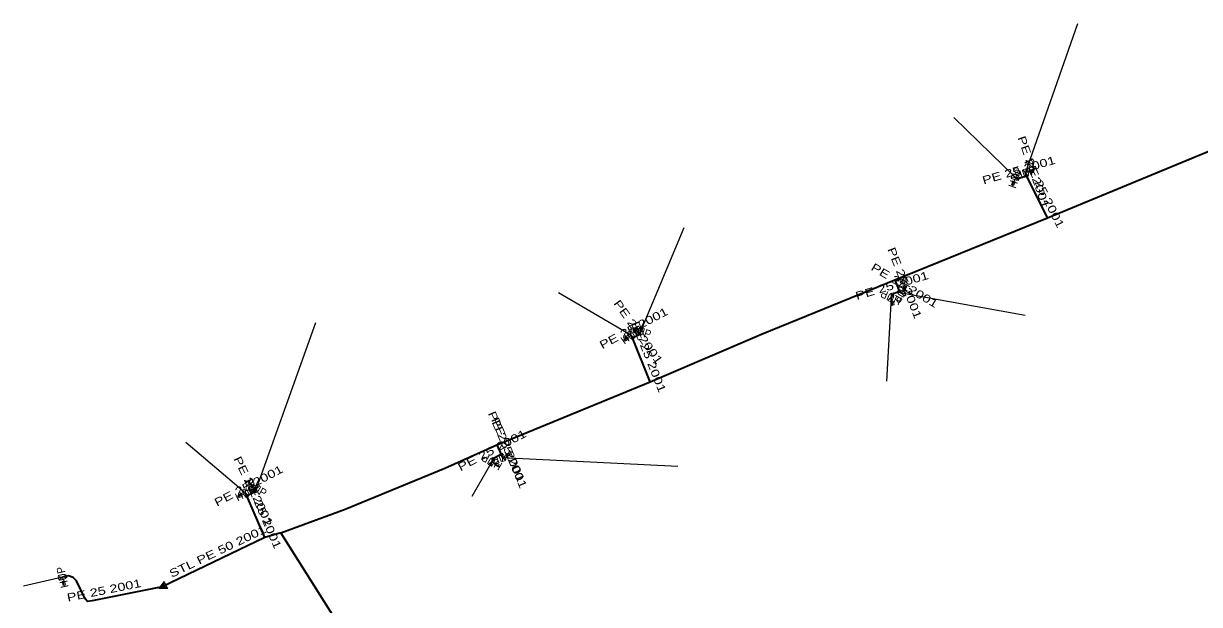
# Model space of a CAD drawing. Extents: x -737484 to -734496, y -1033882 to -1030666.
# Drawn here: x -735181.8 to -735034.9, y -1033442.1 to -1033369.5 of the extents above; entities that cross this region are included whole.
import ezdxf
from ezdxf.enums import TextEntityAlignment as Align

# ---------------------------------------------------------------- set-up
doc = ezdxf.new("R2010")
doc.units = 0
doc.header["$LTSCALE"] = 0.4
for name, color, linetype, lineweight in [('1', 7, 'Continuous', 13), ('22', 7, 'Continuous', 25), ('5', 7, 'Continuous', 35), ('7', 7, 'Continuous', 35)]:
    doc.layers.add(name, color=color, linetype=linetype, lineweight=lineweight)
doc.layers.add('2', color=7, linetype='Continuous')

msp = doc.modelspace()

# ---------------------------------------------------------------- linework, layer by layer
at = {"layer": '1'}
for p, q in [((-735056.61, -1033388.21), (-735056.137, -1033388.047)), ((-735056.041, -1033388.093), (-735055.71, -1033387.979)), ((-735058.148, -1033389.299), (-735058.262, -1033389.63)), ((-735057.89, -1033388.78), (-735058.052, -1033389.252)), ((-735072.11, -1033403.18), (-735071.852, -1033402.751)), ((-735071.749, -1033402.725), (-735071.569, -1033402.425)), ((-735073.41, -1033403.743), (-735073.297, -1033404.23)), ((-735073.353, -1033404.32), (-735073.274, -1033404.661)), ((-735105.93, -1033408.48), (-735106.329, -1033408.78)), ((-735105.221, -1033407.721), (-735105.554, -1033407.613)), ((-735104.698, -1033407.971), (-735105.173, -1033407.816)), ((-735106.434, -1033408.766), (-735106.713, -1033408.976)), ((-735123.31, -1033424.28), (-735122.872, -1033424.522)), ((-735122.843, -1033424.624), (-735122.537, -1033424.794)), ((-735121.97, -1033423.72), (-735121.509, -1033423.524)), ((-735121.411, -1033423.564), (-735121.089, -1033423.427)), ((-735153.16, -1033427.277), (-735153.463, -1033427.102)), ((-735152.7, -1033427.63), (-735153.133, -1033427.38)), ((-735154.609, -1033428.384), (-735154.924, -1033428.538)), ((-735154.06, -1033428.2), (-735154.509, -1033428.419)), ((-735176.93, -1033438.7), (-735176.817, -1033439.187)), ((-735176.873, -1033439.277), (-735176.794, -1033439.618))]:
    msp.add_line(p, q, dxfattribs=at)
for points in [[(-735056.961, -1033387.801), (-735056.583, -1033387.671), (-735056.636, -1033388.746), (-735056.258, -1033388.616)], [(-735055.664, -1033387.884), (-735055.713, -1033387.742), (-735056.186, -1033387.905), (-735056.137, -1033388.047)], [(-735055.664, -1033387.884), (-735055.615, -1033388.026), (-735056.088, -1033388.189), (-735056.137, -1033388.047)], [(-735055.688, -1033387.931), (-735055.663, -1033388.002), (-735056.065, -1033388.141), (-735056.09, -1033388.07)], [(-735058.427, -1033388.806), (-735058.297, -1033388.428), (-735057.482, -1033389.131), (-735057.352, -1033388.753)], [(-735058.215, -1033389.725), (-735058.357, -1033389.676), (-735058.194, -1033389.203), (-735058.052, -1033389.252)], [(-735058.238, -1033389.677), (-735058.309, -1033389.653), (-735058.17, -1033389.251), (-735058.099, -1033389.275)], [(-735058.215, -1033389.725), (-735058.073, -1033389.774), (-735057.91, -1033389.301), (-735058.052, -1033389.252)], [(-735071.578, -1033403.265), (-735071.784, -1033403.607), (-735072.435, -1033402.75), (-735072.641, -1033403.092)], [(-735071.594, -1033402.322), (-735071.723, -1033402.245), (-735071.981, -1033402.674), (-735071.852, -1033402.751)], [(-735071.594, -1033402.322), (-735071.466, -1033402.4), (-735071.723, -1033402.828), (-735071.852, -1033402.751)], [(-735071.582, -1033402.374), (-735071.518, -1033402.413), (-735071.737, -1033402.777), (-735071.801, -1033402.738)], [(-735073.439, -1033404.278), (-735073.805, -1033404.115), (-735073.032, -1033403.364), (-735073.398, -1033403.201)], [(-735073.185, -1033404.717), (-735073.331, -1033404.751), (-735073.443, -1033404.263), (-735073.297, -1033404.23)], [(-735073.229, -1033404.688), (-735073.302, -1033404.705), (-735073.398, -1033404.291), (-735073.325, -1033404.274)], [(-735073.185, -1033404.717), (-735073.038, -1033404.683), (-735073.151, -1033404.196), (-735073.297, -1033404.23)], [(-735106.728, -1033409.081), (-735106.818, -1033408.962), (-735106.419, -1033408.661), (-735106.329, -1033408.78)], [(-735106.38, -1033408.185), (-735106.052, -1033407.955), (-735105.807, -1033409.004), (-735105.479, -1033408.774)], [(-735105.649, -1033407.661), (-735105.695, -1033407.804), (-735105.219, -1033407.959), (-735105.173, -1033407.816)], [(-735105.649, -1033407.661), (-735105.602, -1033407.519), (-735105.127, -1033407.673), (-735105.173, -1033407.816)], [(-735105.601, -1033407.638), (-735105.578, -1033407.567), (-735105.174, -1033407.698), (-735105.197, -1033407.769)], [(-735104.726, -1033407.442), (-735104.348, -1033407.572), (-735105.051, -1033408.387), (-735104.673, -1033408.517)], [(-735106.72, -1033409.029), (-735106.765, -1033408.969), (-735106.426, -1033408.713), (-735106.381, -1033408.773)], [(-735106.728, -1033409.081), (-735106.638, -1033409.201), (-735106.239, -1033408.9), (-735106.329, -1033408.78)], [(-735121.59, -1033424.102), (-735121.958, -1033424.258), (-735121.981, -1033423.181), (-735122.349, -1033423.337)], [(-735121.049, -1033423.329), (-735121.108, -1033423.191), (-735121.568, -1033423.386), (-735121.509, -1033423.524)], [(-735121.049, -1033423.329), (-735120.99, -1033423.467), (-735121.451, -1033423.662), (-735121.509, -1033423.524)], [(-735121.07, -1033423.378), (-735121.04, -1033423.447), (-735121.431, -1033423.613), (-735121.461, -1033423.544)], [(-735123.386, -1033424.812), (-735123.733, -1033424.612), (-735122.886, -1033423.945), (-735123.233, -1033423.745)], [(-735122.435, -1033424.764), (-735122.508, -1033424.896), (-735122.945, -1033424.653), (-735122.872, -1033424.522)], [(-735122.486, -1033424.778), (-735122.522, -1033424.844), (-735122.894, -1033424.638), (-735122.858, -1033424.572)], [(-735122.435, -1033424.764), (-735122.362, -1033424.633), (-735122.799, -1033424.391), (-735122.872, -1033424.522)], [(-735154.458, -1033427.837), (-735154.099, -1033427.661), (-735154.02, -1033428.736), (-735153.661, -1033428.56)], [(-735153.566, -1033427.13), (-735153.641, -1033427.259), (-735153.208, -1033427.509), (-735153.133, -1033427.38)], [(-735153.566, -1033427.13), (-735153.491, -1033427), (-735153.058, -1033427.25), (-735153.133, -1033427.38)], [(-735153.514, -1033427.116), (-735153.477, -1033427.052), (-735153.109, -1033427.264), (-735153.146, -1033427.329)], [(-735152.622, -1033427.096), (-735152.275, -1033427.296), (-735153.122, -1033427.963), (-735152.775, -1033428.163)], [(-735154.958, -1033428.638), (-735155.024, -1033428.503), (-735154.575, -1033428.284), (-735154.509, -1033428.419)], [(-735154.94, -1033428.588), (-735154.973, -1033428.521), (-735154.591, -1033428.334), (-735154.558, -1033428.402)], [(-735154.958, -1033428.638), (-735154.893, -1033428.773), (-735154.443, -1033428.554), (-735154.509, -1033428.419)], [(-735177.371, -1033439.007), (-735177.461, -1033438.617), (-735176.396, -1033438.782), (-735176.486, -1033438.392)], [(-735176.705, -1033439.674), (-735176.851, -1033439.708), (-735176.963, -1033439.22), (-735176.817, -1033439.187)], [(-735176.749, -1033439.645), (-735176.822, -1033439.662), (-735176.918, -1033439.248), (-735176.845, -1033439.231)], [(-735176.705, -1033439.674), (-735176.558, -1033439.64), (-735176.671, -1033439.153), (-735176.817, -1033439.187)], [(-735163.791, -1033440.12), (-735164.229, -1033439.221), (-735164.909, -1033440.109)], [(-735164.248, -1033439.41), (-735164.708, -1033440.01), (-735163.952, -1033440.018)], [(-735164.507, -1033439.913), (-735164.113, -1033439.916), (-735164.267, -1033439.599)]]:
    msp.add_lwpolyline(points, close=True, dxfattribs=at)
at = {"layer": '22'}
for p, q in [((-735056.61, -1033388.209), (-735050.065, -1033369.542)), ((-735057.89, -1033388.78), (-735065.563, -1033381.29)), ((-735104.7, -1033407.98), (-735099.268, -1033395.022)), ((-735105.93, -1033408.48), (-735114.976, -1033403.176)), ((-735073.419, -1033403.74), (-735073.989, -1033414.215)), ((-735072.11, -1033403.179), (-735056.669, -1033405.945)), ((-735152.699, -1033427.63), (-735145.3, -1033406.881)), ((-735154.06, -1033428.199), (-735161.528, -1033421.861)), ((-735123.31, -1033424.279), (-735125.795, -1033428.618)), ((-735121.97, -1033423.72), (-735100.048, -1033424.826)), ((-735176.929, -1033438.7), (-735181.802, -1033439.821))]:
    msp.add_line(p, q, dxfattribs=at)
at = {"layer": '5'}
for points in [[(-735149.64, -1033433.16), (-735141.61, -1033430.2), (-735129.18, -1033425.07), (-735122.65, -1033422.14), (-735103.53, -1033414.27), (-735089.62, -1033408.34), (-735072.93, -1033401.57), (-735053.88, -1033393.79), (-735022.84, -1033381)], [(-735149.64, -1033433.16), (-735151.64, -1033433.74), (-735164.46, -1033439.89)], [(-735115.28, -1033487.08), (-735119.16, -1033480.92), (-735131.9, -1033461.24), (-735149.64, -1033433.16)]]:
    msp.add_lwpolyline(points, dxfattribs=at)
at = {"layer": '7'}
for p, q in [((-735056.47, -1033388.61), (-735056.61, -1033388.209)), ((-735053.88, -1033393.79), (-735056.47, -1033388.61)), ((-735072.93, -1033401.57), (-735072.36, -1033403.03)), ((-735072.36, -1033403.03), (-735072.11, -1033403.179)), ((-735105.71, -1033408.79), (-735105.93, -1033408.48)), ((-735103.53, -1033414.27), (-735105.71, -1033408.79)), ((-735122.65, -1033422.14), (-735122.12, -1033423.36)), ((-735122.12, -1033423.36), (-735121.97, -1033423.72)), ((-735153.91, -1033428.51), (-735154.06, -1033428.199)), ((-735151.64, -1033433.74), (-735153.91, -1033428.51))]:
    msp.add_line(p, q, dxfattribs=at)
for points in [[(-735056.47, -1033388.61), (-735057.51, -1033388.91), (-735057.89, -1033388.78)], [(-735072.36, -1033403.03), (-735073.21, -1033403.28), (-735073.419, -1033403.74)], [(-735105.71, -1033408.79), (-735104.82, -1033408.32), (-735104.7, -1033407.98)], [(-735122.12, -1033423.36), (-735123.07, -1033423.86), (-735123.31, -1033424.279)], [(-735153.91, -1033428.51), (-735152.91, -1033427.99), (-735152.699, -1033427.63)], [(-735164.46, -1033439.89), (-735173.23, -1033441.65), (-735173.79, -1033441.73), (-735174.11, -1033441.41), (-735175.18, -1033439.15), (-735175.59, -1033438.72), (-735176.19, -1033438.53), (-735176.929, -1033438.7)]]:
    msp.add_lwpolyline(points, dxfattribs=at)

# ---------------------------------------------------------------- texts
at = {"layer": '2', "width": 0.95}
for rotation, p in [(71, (-735057.417, -1033388.9423)), (19, (-735056.4463, -1033388.681)), (239, (-735072.5382, -1033402.921)), (156, (-735073.2151, -1033403.2823)), (341, (-735104.8623, -1033408.452)), (35, (-735105.6423, -1033408.8891)), (203, (-735122.1651, -1033423.2593)), (150, (-735123.0595, -1033423.8459)), (26, (-735153.8407, -1033428.6475)), (330, (-735152.9485, -1033428.0621)), (103, (-735176.4415, -1033438.587))]:
    msp.add_text('HUP', height=1, rotation=rotation, dxfattribs=at).set_placement(p, align=Align.CENTER)
at = {"layer": '5', "width": 1.35}
msp.add_text('STL PE 50 2001', height=1, rotation=25.628, dxfattribs=at).set_placement((-735157.3268, -1033435.9129), align=Align.CENTER)
at = {"layer": '7', "width": 1.35}
for rotation, p in [(289.245, (-735056.0674, -1033388.2447)), (16.091, (-735057.3216, -1033388.3349)), (296.565, (-735054.7268, -1033390.9764)), (291.326, (-735072.1789, -1033402.1172)), (329.205, (-735071.9785, -1033402.6747)), (16.39, (-735073.1681, -1033402.7461)), (305.362, (-735105.4115, -1033408.3451)), (27.838, (-735105.3385, -1033408.0286)), (291.693, (-735104.1547, -1033411.3442)), (293.481, (-735121.9258, -1033422.5508)), (292.62, (-735121.583, -1033423.3477)), (27.759, (-735123.0419, -1033423.2796)), (27.474, (-735153.4547, -1033427.7092)), (295.749, (-735153.534, -1033428.1373)), (293.463, (-735152.3162, -1033430.9254)), (11.348, (-735171.6389, -1033440.82))]:
    msp.add_text('PE 25 2001', height=1, rotation=rotation, dxfattribs=at).set_placement(p, align=Align.CENTER)

doc.saveas('drawing.dxf')
